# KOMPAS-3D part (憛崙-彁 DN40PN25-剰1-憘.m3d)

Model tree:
1. Объединить компоненты:1  (labels: СЕНС-ПР DN40PN25-ДП1)
2. Эскиз:1
3. Операция выдавливания:1
     Расстояние 1 = 14
4. Фаска:1
     Угол = 45; Длина 1 = 2; Длина 2 = 2

Referenced files in D:\Савин\!СЕНСОР\3D для заказчика\!Новый перечень\СЕНС-ПР\3. СЕНС-ПР-ДП\DN40\: СЕНС-ПР DN40PN25-ДП1.a3d
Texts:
  СЕНС-ПР DN40PN25-ДП1-СВ
  ООО НПП Сенсор
  СЕНС-ПР DN40PN25-ДП1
